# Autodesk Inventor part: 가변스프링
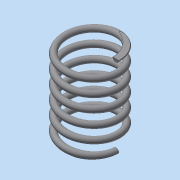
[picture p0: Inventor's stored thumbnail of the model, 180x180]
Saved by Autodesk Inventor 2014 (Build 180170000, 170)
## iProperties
Created: 2023-01
Part Number: 가변스프링
Material: 일반
Document SubType Name: Modeling
Designer: dg
Density: 1 g/cm^3
Appearance: 기본값
Author: dg
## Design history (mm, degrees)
sketch "스케치1"
  geometry: L1 (0, 0)-(0, 26.33); L2 (0, 0)-(8.5, 0); L3 (0, 26.33)-(8.5, 26.33); C1 r 1 at (8.5, 0)
  constraints: 6 end point, 1 centre point, 1 coincident, 1 horizontal, 1 perpendicular, 1 vertical, 1 vertical alignment
  dimensions: "d0" = 26.33013 distance of L1.start L1.end (derived); "d1" = 8.5 distance of L1.start L2.end; "d2" = 2 diameter of C1
feature "코일1" pitch "d3" = 10; turns "d5" = 6; dims "d4" = 26.33013 (= d0), "d6" = 0, angle "d7" = 90 deg, angle "d8" = 90 deg, "d9" = 0, "d10" = 0
node "작업 평면1"
node "작업 평면2"
feature "분할1"
feature "분할2"
node "솔리드1"
other parameters: "d11" = 0, "d12" = 0
